// Mitsubishi GX Works2 project: FX2N-MODBUS通讯485   PLC: FX2N/FX2NC

PROGRAM MAIN
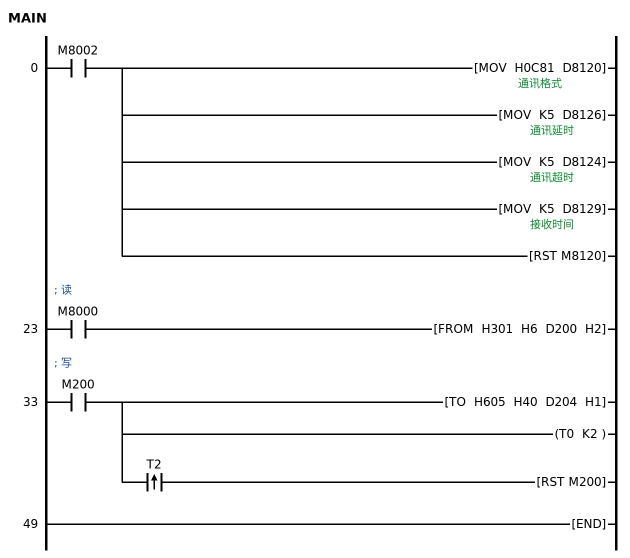
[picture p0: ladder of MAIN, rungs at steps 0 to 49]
0     LD      M8002
      MOV     H0C81 D8120  ; 通讯格式
        [note] 9600.N.8.1
      MOV     K5 D8126  ; 通讯延时
      MOV     K5 D8124  ; 通讯超时
      MOV     K5 D8129  ; 接收时间
      RST     M8120
; 读
23    LD      M8000
      FROM    H301 H6 D200 H2
; 写
33    LD      M200
      TO      H605 H40 D204 H1
      OUT     T0 K2
      ANDP    T2
      RST     M200
49    END
END_PROGRAM
